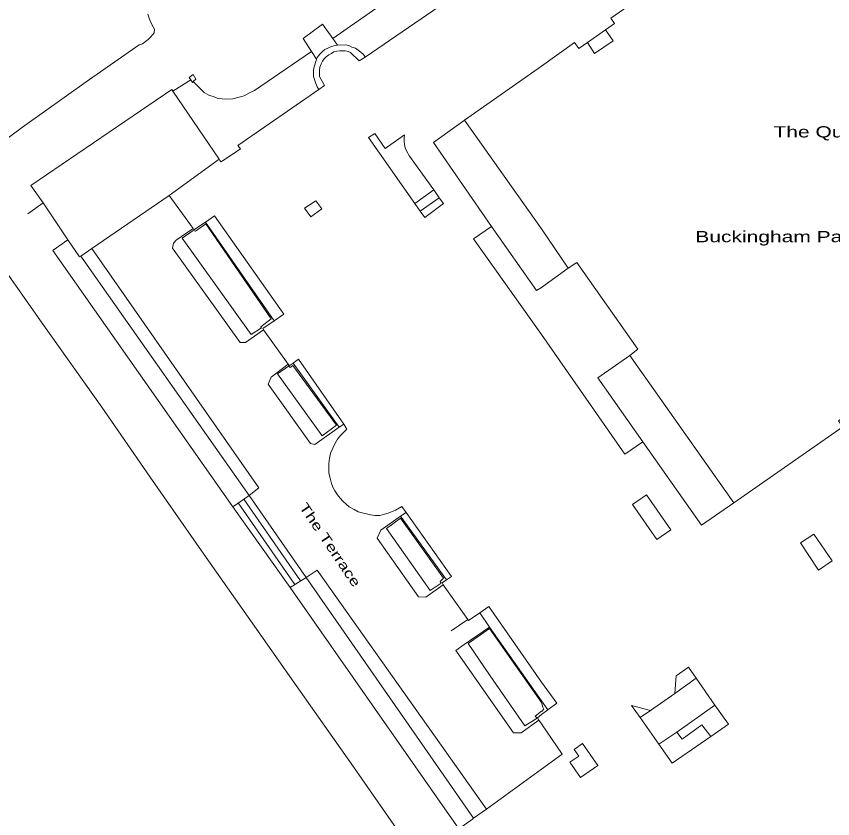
# Model space of a CAD drawing. Extents: x 528790 to 529292, y 179350 to 179856.
# Drawn here: x 528918 to 529045.4, y 179559 to 179684.2 of the extents above; entities that cross this region are included whole.
import ezdxf

# ---------------------------------------------------------------- set-up
doc = ezdxf.new("R2010")
doc.units = 0
doc.header["$LTSCALE"] = 0.6
doc.layers.add('1', color=7, linetype='Continuous', lineweight=13)
doc.layers.add('2', color=7, linetype='Continuous', lineweight=13)
doc.layers.add('5', color=7, linetype='Continuous')

msp = doc.modelspace()

# ---------------------------------------------------------------- linework, layer by layer
at = {"layer": '1'}
for points in [[(529015.8, 179617.8), (529013, 179615.9), (529000, 179634.55), (528989.4, 179649.5), (528992.2, 179651.4), (528983.15, 179664.5), (528988, 179668), (529000, 179676.4), (529005.15, 179680.1), (529005.8, 179679.2), (529007.15, 179680.1), (529010, 179682.1), (529011.4, 179683.1), (529010.8, 179683.9), (529036.4, 179701.7), (529038.85, 179703.45), (529039.6, 179703.9), (529045.5, 179695.4)], [(529045.5, 179695.4), (529039.6, 179703.9), (529038.85, 179703.45), (529036.4, 179701.7), (529010.8, 179683.9), (529011.4, 179683.1), (529010, 179682.1), (529011.2, 179680.4), (529008.25, 179678.4), (529007.15, 179680.1), (529005.8, 179679.2), (529005.15, 179680.1), (529000, 179676.4), (528988, 179668), (529000, 179651.05), (529004.15, 179644.9), (529005.5, 179645.8), (529015.05, 179632.25), (529013.8, 179631.3), (529030, 179608.3), (529047, 179620.15)], [(528922.2, 179655.1), (528920.3, 179657.8), (528942.3, 179672.8), (528942.45, 179672.5), (528945.25, 179674.3), (528945, 179674.65), (528945.6, 179675.1), (528946.05, 179674.4), (528945.6, 179674.05), (528947.35, 179672.3), (528948.05, 179671.9), (528948.9, 179671.65), (528949.5, 179671.4), (528950.15, 179671.3), (528950.75, 179671.25), (528951.8, 179671.3), (528952.8, 179671.6), (528953.6, 179671.8), (528954.4, 179672.25), (528955.2, 179672.65), (528964.1, 179678.7), (528962.8, 179680.75), (528965.8, 179683), (528967.45, 179680.75), (528977.05, 179687.5)], [(528977.05, 179687.5), (528967.45, 179680.75), (528968.15, 179679.7), (528969.4, 179679.75), (528969.9, 179679.65), (528970.4, 179679.4), (528970.95, 179679.25), (528971.4, 179678.9), (528971.8, 179678.6), (528972.2, 179678.25), (528972.45, 179677.85), (528985, 179686.4)], [(528985, 179686.4), (528972.45, 179677.85), (528971.55, 179677.25), (528970.2, 179678.55), (528969.8, 179678.7), (528969.35, 179678.8), (528968.5, 179678.8), (528968.05, 179678.75), (528967.6, 179678.65), (528967.2, 179678.4), (528966.8, 179678.2), (528966.4, 179677.9), (528966.05, 179677.55), (528965.8, 179677.2), (528965.6, 179676.8), (528965.4, 179676.25), (528965.35, 179675.8), (528965.35, 179674.8), (528966.15, 179673.4), (528965.25, 179672.8), (528952.6, 179664.05), (528953, 179663.5), (528950, 179661.5), (528949.8, 179661.7), (528949.7, 179661.9), (528941.9, 179656.25), (528945.6, 179651.1), (528945.75, 179650.9), (528947.55, 179652.1), (528948.95, 179653.05), (528959.8, 179637.75), (528958.25, 179636.7), (528956.5, 179635.5), (528956.6, 179635.3), (528960.45, 179629.9), (528960.6, 179629.65), (528961.25, 179630.1), (528962.05, 179630.7), (528969.15, 179620.55), (528969.6, 179619.8), (528968.6, 179618.8), (528968.15, 179618.2), (528967.75, 179617.5), (528967.4, 179616.8), (528967.05, 179616.05), (528966.9, 179615.25), (528966.8, 179614.4), (528966.8, 179612.9), (528967, 179612.15), (528967.2, 179611.3), (528967.4, 179610.75), (528967.75, 179610.15), (528968.15, 179609.55), (528968.55, 179609), (528969, 179608.55), (528969.55, 179608.05), (528970, 179607.65), (528970.75, 179607.25), (528971.4, 179606.9), (528972, 179606.7), (528973.35, 179606.4), (528974, 179606.3), (528974.75, 179606.3), (528975.5, 179606.5), (528976.05, 179606.65), (528977.2, 179607.15), (528978.2, 179607.7), (528978.85, 179606.8), (528985.95, 179596.8), (528985.15, 179596.25), (528984.5, 179595.8), (528984.65, 179595.5), (528988.5, 179590.1), (528988.6, 179589.9), (528990.35, 179591.1), (528991.75, 179592.1), (529000, 179580.3), (529002.4, 179577), (529001, 179576), (529000, 179575.25), (528999.35, 179574.75), (528999.6, 179574.35), (529000, 179573.8), (529003.2, 179569.05), (529000, 179566.7), (528991.4, 179560.5), (528989.4, 179559.1), (528989.2, 179558.9)], [(528907.93, 179659.11), (528908.95, 179659.7), (528912.4, 179662), (528915.75, 179664.5), (528919, 179666.9), (528928.9, 179674), (528937.2, 179679.75), (528937.7, 179679.9), (528938.2, 179680.25), (528938.6, 179680.6), (528939, 179681), (528939.55, 179681.65), (528939.6, 179682.2), (528939.2, 179682.9), (528938.8, 179683.75), (528938.55, 179684.55)], [(528938.55, 179684.55), (528938.8, 179683.75), (528939.2, 179682.9), (528939.6, 179682.2), (528939.55, 179681.65), (528939, 179681), (528938.6, 179680.6), (528938.2, 179680.25), (528937.7, 179679.9), (528937.2, 179679.75), (528928.9, 179674), (528919, 179666.9), (528915.75, 179664.5), (528912.4, 179662), (528908.95, 179659.7), (528907.93, 179659.11), (528909.7, 179652.25), (528910.75, 179651.4), (528912, 179650.3), (528915.8, 179645.2), (528922.05, 179636.3), (528931.35, 179623.2)], [(528931.35, 179623.2), (528938.9, 179612.3), (528947.3, 179600.3), (528956.2, 179587.65), (528961.7, 179579.8), (528970.3, 179567.6), (528979, 179555.1), (528980.41, 179553.09), (528987.09, 179557.41), (528960.75, 179595.05), (528951.8, 179607.65), (528923.7, 179647.65), (528923.8, 179647.7), (528926.05, 179649.3), (528922.2, 179655.1)], [(528979, 179555.1), (528970.3, 179567.6), (528961.7, 179579.8), (528956.2, 179587.65), (528947.3, 179600.3), (528938.9, 179612.3), (528931.35, 179623.2), (528922.05, 179636.3), (528915.8, 179645.2)], [(529047, 179620.15), (529030, 179608.3), (529024.95, 179604.8), (529015.8, 179617.8)]]:
    msp.add_lwpolyline(points, dxfattribs=at)
for points in [[(528964.9, 179677.5), (528965, 179677.8), (528965.4, 179678.3), (528965.8, 179678.7), (528966.2, 179679), (528966.75, 179679.3), (528967.2, 179679.5), (528967.8, 179679.65), (528968.15, 179679.7), (528967.45, 179680.75), (528965.8, 179683), (528962.8, 179680.75), (528964.1, 179678.7)], [(529010, 179682.1), (529007.15, 179680.1), (529008.25, 179678.4), (529011.2, 179680.4)], [(528965.25, 179672.8), (528966.15, 179673.4), (528965.35, 179674.8), (528965.35, 179675.8), (528965.4, 179676.25), (528965.6, 179676.8), (528965.8, 179677.2), (528966.05, 179677.55), (528966.4, 179677.9), (528966.8, 179678.2), (528967.2, 179678.4), (528967.6, 179678.65), (528968.05, 179678.75), (528968.5, 179678.8), (528969.35, 179678.8), (528969.8, 179678.7), (528970.2, 179678.55), (528971.55, 179677.25), (528972.45, 179677.85), (528972.2, 179678.25), (528971.8, 179678.6), (528971.4, 179678.9), (528970.95, 179679.25), (528970.4, 179679.4), (528969.9, 179679.65), (528969.4, 179679.75), (528968.15, 179679.7), (528967.8, 179679.65), (528967.2, 179679.5), (528966.75, 179679.3), (528966.2, 179679), (528965.8, 179678.7), (528965.4, 179678.3), (528965, 179677.8), (528964.9, 179677.5), (528964.8, 179677.3), (528964.5, 179676.3), (528964.4, 179675.8), (528964.4, 179674.8), (528964.6, 179674.2), (528964.75, 179673.7), (528965, 179673.2)], [(528964.9, 179677.5), (528964.1, 179678.7), (528955.2, 179672.65), (528954.4, 179672.25), (528953.6, 179671.8), (528952.8, 179671.6), (528951.8, 179671.3), (528950.75, 179671.25), (528950.15, 179671.3), (528949.5, 179671.4), (528948.9, 179671.65), (528948.05, 179671.9), (528947.35, 179672.3), (528945.6, 179674.05), (528945.5, 179673.9), (528945.25, 179674.3), (528942.45, 179672.5), (528949.7, 179661.9), (528949.8, 179661.7), (528950, 179661.5), (528953, 179663.5), (528952.6, 179664.05), (528965.25, 179672.8), (528965, 179673.2), (528964.75, 179673.7), (528964.6, 179674.2), (528964.4, 179674.8), (528964.4, 179675.8), (528964.5, 179676.3), (528964.8, 179677.3)], [(528945.25, 179674.3), (528945.5, 179673.9), (528945.6, 179674.05), (528946.05, 179674.4), (528945.6, 179675.1), (528945, 179674.65)], [(528928.1, 179646.75), (528929.8, 179647.95), (528941.9, 179656.25), (528949.7, 179661.9), (528942.45, 179672.5), (528942.3, 179672.8), (528920.3, 179657.8), (528922.2, 179655.1), (528926.05, 179649.3), (528927.9, 179646.65)], [(528988, 179668), (528983.15, 179664.5), (528992.2, 179651.4), (528999.2, 179641.4), (529000, 179641.9), (529004.15, 179644.9), (529000, 179651.05)], [(528973, 179665.3), (528974, 179665.9), (528975.6, 179663.6), (528978.6, 179665.7), (528978.55, 179665.2), (528978.55, 179664.7), (528978.6, 179664.2), (528978.7, 179663.7), (528978.9, 179663.2), (528979.4, 179662.4), (528983.2, 179657.1), (528984, 179655.9), (528984.7, 179655), (528981.8, 179652.8), (528981.05, 179653.8), (528980.2, 179655)], [(528980.2, 179655), (528983.2, 179657.1), (528979.4, 179662.4), (528978.9, 179663.2), (528978.7, 179663.7), (528978.6, 179664.2), (528978.55, 179664.7), (528978.55, 179665.2), (528978.6, 179665.7), (528975.6, 179663.6), (528974, 179665.9), (528973, 179665.3)], [(528942.4, 179648), (528942.55, 179648.8), (528942.95, 179649.25), (528945.6, 179651.1), (528941.9, 179656.25), (528929.8, 179647.95), (528955.9, 179610.65), (528954.35, 179609.45), (528963.25, 179596.65), (528965, 179597.8), (528991.4, 179560.5), (529000, 179566.7), (529003.2, 179569.05), (529000, 179573.8), (528999.6, 179574.35), (528996.8, 179572.4), (528995.6, 179572.4), (528986.604, 179585.239), (528987.926, 179586.155), (528991.897, 179588.904), (528990.35, 179591.1), (528988.6, 179589.9), (528988.5, 179590.1), (528984.65, 179595.5), (528981.95, 179593.55), (528980.8, 179593.6), (528974.35, 179602.75), (528974.9, 179604), (528978, 179606.2), (528978.85, 179606.8), (528978.2, 179607.7), (528977.2, 179607.15), (528976.05, 179606.65), (528975.5, 179606.5), (528974.75, 179606.3), (528974, 179606.3), (528973.35, 179606.4), (528972, 179606.7), (528971.4, 179606.9), (528970.75, 179607.25), (528970, 179607.65), (528969.55, 179608.05), (528969, 179608.55), (528968.55, 179609), (528968.15, 179609.55), (528967.75, 179610.15), (528967.4, 179610.75), (528967.2, 179611.3), (528967, 179612.15), (528966.8, 179612.9), (528966.8, 179614.4), (528966.9, 179615.25), (528967.05, 179616.05), (528967.4, 179616.8), (528967.75, 179617.5), (528968.15, 179618.2), (528968.6, 179618.8), (528969.6, 179619.8), (528969.15, 179620.55), (528968.4, 179620.1), (528964.6, 179617.4), (528963.95, 179617.55), (528957.35, 179626.8), (528957.8, 179627.9), (528960.45, 179629.9), (528956.6, 179635.3), (528953.8, 179633.3), (528952.95, 179633.3)], [(528984, 179655.9), (528983.2, 179657.1), (528980.2, 179655), (528981.05, 179653.8)], [(528965.691, 179654.162), (528964, 179652.9), (528963, 179654.25), (528964.75, 179655.4)], [(528965.691, 179654.162), (528964.75, 179655.4), (528963, 179654.25), (528964, 179652.9)], [(528981.05, 179653.8), (528981.8, 179652.8), (528984.7, 179655), (528984, 179655.9)], [(528958.25, 179636.7), (528959.8, 179637.75), (528948.95, 179653.05), (528947.55, 179652.1)], [(528947.55, 179652.1), (528945.75, 179650.9), (528945.6, 179651.1), (528942.95, 179649.25), (528942.55, 179648.8), (528942.4, 179648), (528952.95, 179633.3), (528953.8, 179633.3), (528956.6, 179635.3), (528956.5, 179635.5), (528958.25, 179636.7)], [(528943.9, 179649.6), (528954.7, 179634.55), (528956.3, 179635.6), (528956.2, 179635.75), (528957.8, 179637), (528947.6, 179651.8), (528946, 179650.7), (528945.6, 179650.8)], [(529013.8, 179631.3), (529015.05, 179632.25), (529005.5, 179645.8), (529004.15, 179644.9), (529000, 179641.9), (528999.2, 179641.4), (528992.2, 179651.4), (528989.4, 179649.5), (529000, 179634.55), (529013, 179615.9), (529015.8, 179617.8), (529008.8, 179627.8)], [(528926.05, 179649.3), (528923.8, 179647.7), (528923.7, 179647.65), (528951.8, 179607.65), (528954.35, 179609.45), (528928.1, 179646.75), (528927.9, 179646.65)], [(528929.8, 179647.95), (528928.1, 179646.75), (528954.35, 179609.45), (528955.9, 179610.65)], [(528961.25, 179630.1), (528968.4, 179620.1), (528969.15, 179620.55), (528962.05, 179630.7)], [(529015.8, 179617.8), (529024.95, 179604.8), (529030, 179608.3), (529013.8, 179631.3), (529008.8, 179627.8)], [(528960.45, 179629.9), (528957.8, 179627.9), (528957.35, 179626.8), (528963.95, 179617.55), (528964.6, 179617.4), (528968.4, 179620.1), (528961.25, 179630.1), (528960.6, 179629.65)], [(528965.75, 179618.75), (528968, 179620.4), (528961.2, 179629.7), (528960.75, 179629.4), (528960.5, 179629.6), (528958.8, 179628.4)], [(528954.35, 179609.45), (528951.8, 179607.65), (528960.75, 179595.05), (528963.25, 179596.65)], [(529014.2, 179608), (529016.4, 179609.55), (529020.2, 179604.05), (529018, 179602.55)], [(529018, 179602.55), (529020.2, 179604.05), (529016.4, 179609.55), (529014.2, 179608)], [(528985.15, 179596.25), (528985.95, 179596.8), (528978.85, 179606.8), (528978, 179606.2)], [(528978, 179606.2), (528974.9, 179604), (528974.35, 179602.75), (528980.8, 179593.6), (528981.95, 179593.55), (528984.65, 179595.5), (528984.5, 179595.8), (528985.15, 179596.25)], [(528982.6, 179594.6), (528984.35, 179595.75), (528984.2, 179596), (528984.7, 179596.55), (528978, 179605.9), (528975.8, 179604.3)], [(529045.35, 179599.25), (529043.25, 179597.8), (529040.4, 179602.05), (529042.5, 179603.4)], [(529043.25, 179597.8), (529045.35, 179599.25), (529042.5, 179603.4), (529040.4, 179602.05)], [(528963.25, 179596.65), (528989.4, 179559.1), (528991.4, 179560.5), (528965, 179597.8)], [(528960.75, 179595.05), (528987.09, 179557.41), (528989.2, 179558.9), (528989.4, 179559.1), (528963.25, 179596.65)], [(529001, 179576), (529002.4, 179577), (529000, 179580.3), (528991.75, 179592.1), (528990.35, 179591.1), (528991.897, 179588.904), (529000, 179577.4)], [(528996.8, 179572.4), (528999.6, 179574.35), (528999.35, 179574.75), (529000, 179575.25), (529001, 179576), (529000, 179577.4), (528991.897, 179588.904), (528987.926, 179586.155), (528986.604, 179585.239), (528995.6, 179572.4)], [(528999.3, 179574.7), (528999, 179575), (529000, 179575.75), (529000.1, 179575.8), (529000.25, 179576), (529000.35, 179576.1), (529000.2, 179576.4), (529000, 179577.15), (528991.882, 179588.651), (528988.54, 179586.337), (528992, 179581.3), (528997.4, 179573.5)], [(529020.8, 179578.55), (529021, 179581.3), (529022.95, 179582.65), (529024.15, 179580.9), (529027.05, 179576.7), (529029.2, 179573.75), (529026.4, 179571.8), (529020.4, 179567.65), (529018.3, 179570.6), (529015.4, 179574.8), (529014.05, 179576.65), (529017, 179575.9)], [(529024.15, 179580.9), (529022.95, 179582.65), (529021, 179581.3), (529020.8, 179578.55)], [(529027.05, 179576.7), (529024.15, 179580.9), (529020.8, 179578.55), (529017, 179575.9), (529015.4, 179574.8), (529018.3, 179570.6), (529021.1, 179572.5)], [(529017, 179575.9), (529014.05, 179576.65), (529015.4, 179574.8)], [(529026.4, 179571.8), (529029.2, 179573.75), (529027.05, 179576.7), (529021.1, 179572.5), (529021.95, 179571.4), (529025, 179573.65)], [(529021.1, 179572.5), (529018.3, 179570.6), (529020.4, 179567.65), (529026.4, 179571.8), (529025, 179573.65), (529021.95, 179571.4)], [(529006.1, 179565.4), (529008.8, 179567.3), (529006.4, 179570.75), (529005.1, 179569.8), (529005.8, 179568.75), (529004.4, 179567.8)], [(529008.8, 179567.3), (529006.1, 179565.4), (529004.4, 179567.8), (529005.8, 179568.75), (529005.1, 179569.8), (529006.4, 179570.75)]]:
    msp.add_lwpolyline(points, close=True, dxfattribs=at)
at = {"layer": '2'}
for p, q in [((528985, 179686.4), (528972.45, 179677.85)), ((529010, 179682.1), (529007.15, 179680.1)), ((528967.45, 179680.75), (528968.15, 179679.7)), ((528964.9, 179677.5), (528964.1, 179678.7)), ((528942.45, 179672.5), (528945.25, 179674.3)), ((528949.7, 179661.9), (528942.45, 179672.5)), ((528949.7, 179661.9), (528941.9, 179656.25)), ((528929.8, 179647.95), (528941.9, 179656.25)), ((528941.9, 179656.25), (528945.6, 179651.1)), ((528980.2, 179655), (528983.2, 179657.1)), ((528983.2, 179657.1), (528984, 179655.9)), ((528919.8, 179653.4), (528922.2, 179655.1)), ((528922.2, 179655.1), (528926.05, 179649.3)), ((528981.05, 179653.8), (528980.2, 179655)), ((528981.05, 179653.8), (528984, 179655.9)), ((528945.6, 179651.1), (528942.95, 179649.25)), ((528947.55, 179652.1), (528958.25, 179636.7)), ((528954.7, 179634.55), (528943.9, 179649.6)), ((528951.8, 179607.65), (528923.7, 179647.65)), ((528928.1, 179646.75), (528929.8, 179647.95)), ((528955.9, 179610.65), (528929.8, 179647.95)), ((528928.1, 179646.75), (528954.35, 179609.45)), ((528953.8, 179633.3), (528956.6, 179635.3)), ((528956.6, 179635.3), (528960.45, 179629.9)), ((529013.8, 179631.3), (529030, 179608.3)), ((528960.45, 179629.9), (528957.8, 179627.9)), ((528961.25, 179630.1), (528968.4, 179620.1)), ((528965.75, 179618.75), (528958.8, 179628.4)), ((528968.4, 179620.1), (528969.15, 179620.55)), ((528964.6, 179617.4), (528968.4, 179620.1)), ((528955.9, 179610.65), (528954.35, 179609.45)), ((528954.35, 179609.45), (528951.8, 179607.65)), ((528953.513, 179608.859), (528962.37, 179596.09)), ((528954.35, 179609.45), (528963.25, 179596.65)), ((528951.8, 179607.65), (528960.75, 179595.05)), ((528961.52, 179595.543), (528952.663, 179608.259)), ((528978.85, 179606.8), (528978, 179606.2)), ((528978, 179606.2), (528974.9, 179604)), ((528978, 179606.2), (528985.15, 179596.25)), ((528982.6, 179594.6), (528975.8, 179604.3)), ((528963.25, 179596.65), (528965, 179597.8)), ((528965, 179597.8), (528991.4, 179560.5)), ((528963.25, 179596.65), (528960.75, 179595.05)), ((528963.25, 179596.65), (528989.4, 179559.1)), ((528960.75, 179595.05), (528987.09, 179557.41)), ((528981.95, 179593.55), (528984.65, 179595.5)), ((528984.65, 179595.5), (528988.5, 179590.1)), ((528990.35, 179591.1), (528991.897, 179588.904)), ((528988.5, 179590.1), (528985.9, 179588.3)), ((528987.926, 179586.155), (528991.897, 179588.904)), ((529020.8, 179578.55), (529024.15, 179580.9)), ((529024.15, 179580.9), (529027.05, 179576.7)), ((529017, 179575.9), (529020.8, 179578.55)), ((529015.4, 179574.8), (529017, 179575.9)), ((529027.05, 179576.7), (529021.1, 179572.5)), ((529018.3, 179570.6), (529015.4, 179574.8)), ((528996.8, 179572.4), (528999.6, 179574.35)), ((529018.3, 179570.6), (529021.1, 179572.5)), ((528991.4, 179560.5), (528989.4, 179559.1)), ((528989.4, 179559.1), (528989.2, 179558.9))]:
    msp.add_line(p, q, dxfattribs=at)
for points in [[(529045.5, 179695.4), (529039.6, 179703.9), (529038.85, 179703.45), (529036.4, 179701.7), (529010.8, 179683.9), (529011.4, 179683.1), (529010, 179682.1)], [(528967.45, 179680.75), (528977.05, 179687.5), (528977.6, 179687.9), (528978, 179688.5), (528978.4, 179689.05), (528978.75, 179689.7), (528979, 179690.55), (528979.15, 179691.4), (528979.2, 179692.3), (528979.2, 179693.05), (528979.05, 179693.75), (528978.95, 179694.5), (528978.05, 179696.75)], [(528938.55, 179684.55), (528938.8, 179683.75), (528939.2, 179682.9), (528939.6, 179682.2), (528939.55, 179681.65), (528939, 179681), (528938.6, 179680.6), (528938.2, 179680.25), (528937.7, 179679.9), (528937.2, 179679.75), (528928.9, 179674), (528919, 179666.9), (528915.75, 179664.5), (528912.4, 179662), (528908.95, 179659.7), (528907.93, 179659.11)], [(528964.1, 179678.7), (528962.8, 179680.75), (528965.8, 179683), (528967.45, 179680.75)], [(529010, 179682.1), (529011.2, 179680.4), (529008.25, 179678.4), (529007.15, 179680.1)], [(528964.9, 179677.5), (528965, 179677.8), (528965.4, 179678.3), (528965.8, 179678.7), (528966.2, 179679), (528966.75, 179679.3), (528967.2, 179679.5), (528967.8, 179679.65), (528968.15, 179679.7)], [(528968.15, 179679.7), (528969.4, 179679.75), (528969.9, 179679.65), (528970.4, 179679.4), (528970.95, 179679.25), (528971.4, 179678.9), (528971.8, 179678.6), (528972.2, 179678.25), (528972.45, 179677.85)], [(529007.15, 179680.1), (529005.8, 179679.2), (529005.15, 179680.1), (529000, 179676.4), (528988, 179668)], [(528945.6, 179674.05), (528947.35, 179672.3), (528948.05, 179671.9), (528948.9, 179671.65), (528949.5, 179671.4), (528950.15, 179671.3), (528950.75, 179671.25), (528951.8, 179671.3), (528952.8, 179671.6), (528953.6, 179671.8), (528954.4, 179672.25), (528955.2, 179672.65), (528964.1, 179678.7)], [(528972.45, 179677.85), (528971.55, 179677.25), (528970.2, 179678.55), (528969.8, 179678.7), (528969.35, 179678.8), (528968.5, 179678.8), (528968.05, 179678.75), (528967.6, 179678.65), (528967.2, 179678.4), (528966.8, 179678.2), (528966.4, 179677.9), (528966.05, 179677.55), (528965.8, 179677.2), (528965.6, 179676.8), (528965.4, 179676.25), (528965.35, 179675.8), (528965.35, 179674.8), (528966.15, 179673.4), (528965.25, 179672.8)], [(528965.25, 179672.8), (528965, 179673.2), (528964.75, 179673.7), (528964.6, 179674.2), (528964.4, 179674.8), (528964.4, 179675.8), (528964.5, 179676.3), (528964.8, 179677.3), (528964.9, 179677.5)], [(528945.6, 179674.05), (528946.05, 179674.4), (528945.6, 179675.1), (528945, 179674.65), (528945.25, 179674.3)], [(528945.25, 179674.3), (528945.5, 179673.9), (528945.6, 179674.05)], [(528942.45, 179672.5), (528942.3, 179672.8), (528920.3, 179657.8), (528922.2, 179655.1)], [(528965.25, 179672.8), (528952.6, 179664.05), (528953, 179663.5), (528950, 179661.5), (528949.8, 179661.7), (528949.7, 179661.9)], [(528988, 179668), (528983.15, 179664.5), (528992.2, 179651.4)], [(528988, 179668), (529000, 179651.05), (529004.15, 179644.9)], [(528980.2, 179655), (528973, 179665.3), (528974, 179665.9), (528975.6, 179663.6), (528978.6, 179665.7), (528978.55, 179665.2), (528978.55, 179664.7), (528978.6, 179664.2), (528978.7, 179663.7), (528978.9, 179663.2), (528979.4, 179662.4), (528983.2, 179657.1)], [(528984, 179655.9), (528984.7, 179655), (528981.8, 179652.8), (528981.05, 179653.8)], [(528909.7, 179652.25), (528910.75, 179651.4), (528912, 179650.3), (528915.8, 179645.2), (528922.05, 179636.3), (528931.35, 179623.2), (528938.9, 179612.3), (528947.3, 179600.3), (528956.2, 179587.65), (528961.7, 179579.8), (528970.3, 179567.6), (528979, 179555.1), (528980.41, 179553.09)], [(528947.55, 179652.1), (528948.95, 179653.05), (528959.8, 179637.75), (528958.25, 179636.7)], [(528943.9, 179649.6), (528945.6, 179650.8), (528946, 179650.7), (528947.6, 179651.8), (528957.8, 179637), (528956.2, 179635.75), (528956.3, 179635.6), (528954.7, 179634.55)], [(528945.6, 179651.1), (528945.75, 179650.9), (528947.55, 179652.1)], [(528992.2, 179651.4), (528989.4, 179649.5), (529000, 179634.55), (529013, 179615.9), (529015.8, 179617.8)], [(528992.2, 179651.4), (528999.2, 179641.4), (529000, 179641.9), (529004.15, 179644.9)], [(528926.05, 179649.3), (528923.8, 179647.7), (528923.7, 179647.65)], [(528926.05, 179649.3), (528927.9, 179646.65), (528928.1, 179646.75)], [(528942.95, 179649.25), (528942.55, 179648.8), (528942.4, 179648), (528952.95, 179633.3), (528953.8, 179633.3)], [(529004.15, 179644.9), (529005.5, 179645.8), (529015.05, 179632.25), (529013.8, 179631.3)], [(528958.25, 179636.7), (528956.5, 179635.5), (528956.6, 179635.3)], [(528961.25, 179630.1), (528962.05, 179630.7), (528969.15, 179620.55)], [(529015.8, 179617.8), (529008.8, 179627.8), (529013.8, 179631.3)], [(528958.8, 179628.4), (528960.5, 179629.6), (528960.75, 179629.4), (528961.2, 179629.7), (528968, 179620.4), (528965.75, 179618.75)], [(528960.45, 179629.9), (528960.6, 179629.65), (528961.25, 179630.1)], [(528957.8, 179627.9), (528957.35, 179626.8), (528963.95, 179617.55), (528964.6, 179617.4)], [(529030, 179608.3), (529047, 179620.15), (529046.35, 179621.1), (529047.65, 179622)], [(528969.15, 179620.55), (528969.6, 179619.8), (528968.6, 179618.8), (528968.15, 179618.2), (528967.75, 179617.5), (528967.4, 179616.8), (528967.05, 179616.05), (528966.9, 179615.25), (528966.8, 179614.4), (528966.8, 179612.9), (528967, 179612.15), (528967.2, 179611.3), (528967.4, 179610.75), (528967.75, 179610.15), (528968.15, 179609.55), (528968.55, 179609), (528969, 179608.55), (528969.55, 179608.05), (528970, 179607.65), (528970.75, 179607.25), (528971.4, 179606.9), (528972, 179606.7), (528973.35, 179606.4), (528974, 179606.3), (528974.75, 179606.3), (528975.5, 179606.5), (528976.05, 179606.65), (528977.2, 179607.15), (528978.2, 179607.7), (528978.85, 179606.8)], [(529030, 179608.3), (529024.95, 179604.8), (529015.8, 179617.8)], [(528978.85, 179606.8), (528985.95, 179596.8), (528985.15, 179596.25)], [(528975.8, 179604.3), (528978, 179605.9), (528984.7, 179596.55), (528984.2, 179596), (528984.35, 179595.75), (528982.6, 179594.6)], [(528974.9, 179604), (528974.35, 179602.75), (528980.8, 179593.6), (528981.95, 179593.55)], [(528985.15, 179596.25), (528984.5, 179595.8), (528984.65, 179595.5)], [(528988.5, 179590.1), (528988.6, 179589.9), (528990.35, 179591.1)], [(528990.35, 179591.1), (528991.75, 179592.1), (529000, 179580.3), (529002.4, 179577), (529001, 179576)], [(528997.4, 179573.5), (528999.3, 179574.7), (528999, 179575), (529000, 179575.75), (529000.1, 179575.8), (529000.25, 179576), (529000.35, 179576.1), (529000.2, 179576.4), (529000, 179577.15), (528991.882, 179588.651), (528988.54, 179586.337)], [(528991.897, 179588.904), (529000, 179577.4), (529001, 179576)], [(528996.8, 179572.4), (528995.6, 179572.4), (528986.604, 179585.239), (528987.926, 179586.155)], [(528997.4, 179573.5), (528992, 179581.3), (528988.54, 179586.337)], [(529020.8, 179578.55), (529021, 179581.3), (529022.95, 179582.65), (529024.15, 179580.9)], [(528999.6, 179574.35), (528999.35, 179574.75), (529000, 179575.25), (529001, 179576)], [(529015.4, 179574.8), (529014.05, 179576.65), (529017, 179575.9)], [(529027.05, 179576.7), (529029.2, 179573.75), (529026.4, 179571.8)], [(528991.4, 179560.5), (529000, 179566.7), (529003.2, 179569.05), (529000, 179573.8), (528999.6, 179574.35)], [(529021.1, 179572.5), (529021.95, 179571.4), (529025, 179573.65), (529026.4, 179571.8)], [(529026.4, 179571.8), (529020.4, 179567.65), (529018.3, 179570.6)]]:
    msp.add_lwpolyline(points, dxfattribs=at)
for points in [[(528965.691, 179654.162), (528964, 179652.9), (528963, 179654.25), (528964.75, 179655.4)], [(529018, 179602.55), (529014.2, 179608), (529016.4, 179609.55), (529020.2, 179604.05)], [(529043.25, 179597.8), (529040.4, 179602.05), (529042.5, 179603.4), (529045.35, 179599.25)], [(529006.1, 179565.4), (529004.4, 179567.8), (529005.8, 179568.75), (529005.1, 179569.8), (529006.4, 179570.75), (529008.8, 179567.3)]]:
    msp.add_lwpolyline(points, close=True, dxfattribs=at)

# ---------------------------------------------------------------- texts
at = {"layer": '5', "width": 1.4}
for s, p in [('The Quadrangle', (529036.2, 179665.3)), ('Buckingham Palace', (529024, 179648.95))]:
    msp.add_text(s, height=1.75, dxfattribs=at).set_placement(p)
msp.add_text('The Terrace', height=1.5, rotation=304, dxfattribs=at).set_placement((528962.1, 179607.65))

doc.saveas('drawing.dxf')
